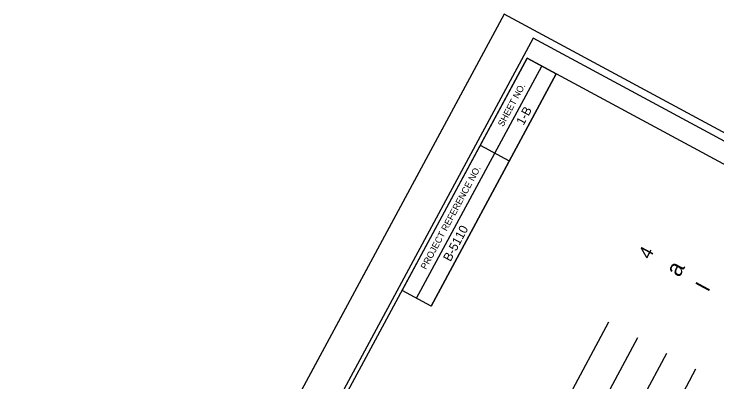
# Model space of a CAD drawing. Extents: x 1376167 to 1379209, y 761324 to 763997.
# Drawn here: x 1377943.6 to 1378370.1, y 763104.6 to 763327.9 of the extents above; entities that cross this region are included whole.
import ezdxf

# ---------------------------------------------------------------- set-up
doc = ezdxf.new("R2010")
doc.units = 0
for name, color, linetype in [('Sheet Cutting Line CELL', 7, 'Continuous'), ('Sheet Data Field CELL', 7, 'Continuous'), ('Sheet Plot Border Inside CELL', 7, 'Continuous'), ('Sheet Plot Border Outside CELL', 7, 'Continuous'), ('Sheet Symbology CELL', 7, 'Continuous')]:
    doc.layers.add(name, color=color, linetype=linetype)

msp = doc.modelspace()

# ---------------------------------------------------------------- linework, layer by layer
at = {"layer": 'Sheet Cutting Line CELL'}
msp.add_line((1378241.03, 763327.89), (1377441.9, 761845.58), dxfattribs=at)
at = {"layer": 'Sheet Plot Border Inside CELL'}
msp.add_lwpolyline([(1378396.56, 761345.67), (1379187.39, 762812.58), (1378258.66, 763313.27), (1377467.83, 761846.37)], close=True, dxfattribs=at)
at = {"layer": 'Sheet Plot Border Outside CELL'}
msp.add_lwpolyline([(1378410.15, 761323.58), (1379209.29, 762805.89), (1378241.03, 763327.89), (1377441.9, 761845.58)], close=True, dxfattribs=at)
at = {"layer": 'Sheet Symbology CELL'}
for p, q in [((1378187.86, 763155.43), (1378263.81, 763296.3)), ((1378196.67, 763150.68), (1378272.61, 763291.55)), ((1378226.53, 763248.23), (1378244.14, 763238.74)), ((1378304.42, 763140.96), (1378227.36, 762998.02)), ((1378322.02, 763131.47), (1378237.54, 762974.75)), ((1378339.63, 763121.98), (1378255.14, 762965.26)), ((1378357.23, 763112.48), (1378278.56, 762966.55))]:
    msp.add_line(p, q, dxfattribs=at)
for points in [[(1378254.97, 763301.06), (1377543.15, 761980.71), (1378466.5, 761482.92), (1379178.32, 762803.27)], [(1378179.03, 763160.19), (1378254.97, 763301.06), (1378272.61, 763291.55), (1378196.67, 763150.68)]]:
    msp.add_lwpolyline(points, close=True, dxfattribs=at)

# ---------------------------------------------------------------- texts
at = {"layer": 'Sheet Data Field CELL'}
for s, p in [('1-B', (1378252.74, 763259.99)), ('B-5110   ', (1378208.42, 763177.28))]:
    msp.add_text(s, height=5.4, rotation=61.6702, dxfattribs=at).set_placement(p)
at = {"layer": 'Sheet Symbology CELL'}
for s, height, rotation, p in [('SHEET NO.', 4, 61.6702, (1378240.4, 763259.2)), ('PROJECT REFERENCE NO.', 4, 61.6702, (1378193.59, 763172.52)), ('4', 8.25, 61.6702, (1378329.35, 763178.51)), ('a', 10.2, 61.6703, (1378347.35, 763167.7)), ('I', 9.38, 61.6702, (1378364.79, 763158.77))]:
    msp.add_text(s, height=height, rotation=rotation, dxfattribs=at).set_placement(p)

doc.saveas('drawing.dxf')
